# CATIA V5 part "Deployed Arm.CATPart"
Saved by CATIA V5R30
Part number: 2
Bounding box of the stored display mesh (mm): x -9.4 to 9.4, y -9.4 to 9.4, z -10 to 465
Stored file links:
  D:\OneDrive\OneDrive - Carleton University\Courses\aero2001\Design Project\3D Models\Deployed\Deployed Arm.CATPart
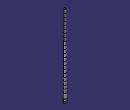
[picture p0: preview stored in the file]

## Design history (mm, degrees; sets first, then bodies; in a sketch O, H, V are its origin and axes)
Body1 (main body)
  Sketch1 on xy-plane, origin (0, 0, 0), H (1, 0, 0), V (0, 1, 0)
    circle A1 centre (0, 0) radius 9
    radius A1 = 9
  Pad1: profile Sketch1, direction (0, 0, 1), length 10, thin wall 0, second thickness 0.2
  Sketch2 on xy-plane, origin (0, 0, 0), H (1, 0, 0), V (0, 1, 0)
    circle A1 centre (0, 0) radius 8.8
    radius A1 = 8.8
  Pad2: profile Sketch2, direction (0, 0, 1), length 40, thin wall 0, second thickness 0.2
  Sketch3 on xy-plane, origin (0, 0, 0), H (1, 0, 0), V (0, 1, 0)
    circle A1 centre (0, 0) radius 8.6
    radius A1 = 8.6
  Pad3: profile Sketch3, direction (0, 0, 1), length 60, thin wall 0, second thickness 0.2
  Sketch4 on xy-plane, origin (0, 0, 0), H (1, 0, 0), V (0, 1, 0)
    circle A1 centre (0, 0) radius 8.4
    radius A1 = 8.4
  Pad4: profile Sketch4, direction (0, 0, 1), length 80, thin wall 0, second thickness 0.2
  Sketch5 on xy-plane, origin (0, 0, 0), H (1, 0, 0), V (0, 1, 0)
    circle A1 centre (0, 0) radius 8.2
    radius A1 = 8.2
  Pad5: profile Sketch5, direction (0, 0, 1), length 100, thin wall 0, second thickness 0.2
  Sketch6 on xy-plane, origin (0, 0, 0), H (1, 0, 0), V (0, 1, 0)
    circle A1 centre (0, 0) radius 8
    radius A1 = 8
  Pad6: profile Sketch6, direction (0, 0, 1), length 120, thin wall 0, second thickness 0.2
  Sketch7 on xy-plane, origin (0, 0, 0), H (1, 0, 0), V (0, 1, 0)
    circle A1 centre (0, 0) radius 7.8
    radius A1 = 7.8
  Pad7: profile Sketch7, direction (0, 0, 1), length 140, thin wall 0, second thickness 0.2
  Sketch8 on xy-plane, origin (0, 0, 0), H (1, 0, 0), V (0, 1, 0)
    circle A1 centre (0, 0) radius 7.6
    radius A1 = 7.6
  Pad8: profile Sketch8, direction (0, 0, 1), length 160, thin wall 0, second thickness 0.2
  Sketch9 on xy-plane, origin (0, 0, 0), H (1, 0, 0), V (0, 1, 0)
    circle A1 centre (0, 0) radius 7.4
    radius A1 = 7.4
  Pad9: profile Sketch9, direction (0, 0, 1), length 180, thin wall 0, second thickness 0.2
  Sketch10 on xy-plane, origin (0, 0, 0), H (1, 0, 0), V (0, 1, 0)
    circle A1 centre (0, 0) radius 7.2
    radius A1 = 7.2
  Pad10: profile Sketch10, direction (0, 0, 1), length 200, thin wall 0, second thickness 0.2
  Sketch11 on xy-plane, origin (0, 0, 0), H (1, 0, 0), V (0, 1, 0)
    circle A1 centre (0, 0) radius 7
    radius A1 = 7
  Pad11: profile Sketch11, direction (0, 0, 1), length 220, thin wall 0, second thickness 0.2
  Sketch12 on xy-plane, origin (0, 0, 0), H (1, 0, 0), V (0, 1, 0)
    circle A1 centre (0, 0) radius 6.8
    radius A1 = 6.8
  Pad12: profile Sketch12, direction (0, 0, 1), length 240, thin wall 0, second thickness 0.2
  Sketch13 on xy-plane, origin (0, 0, 0), H (1, 0, 0), V (0, 1, 0)
    circle A1 centre (0, 0) radius 6.6
    radius A1 = 6.6
  Pad13: profile Sketch13, direction (0, 0, 1), length 260, thin wall 0, second thickness 0.2
  Sketch14 on xy-plane, origin (0, 0, 0), H (1, 0, 0), V (0, 1, 0)
    circle A1 centre (0, 0) radius 6.4
    radius A1 = 6.4
  Pad14: profile Sketch14, direction (0, 0, 1), length 280, thin wall 0, second thickness 0.2
  Sketch15 on xy-plane, origin (0, 0, 0), H (1, 0, 0), V (0, 1, 0)
    circle A1 centre (0, 0) radius 6.2
    point P1 (0, 6.2)
    radius A1 = 6.2
    coincidence: A1 P1, P1 V
  Pad15: profile Sketch15, direction (0, 0, 1), length 300, thin wall 0, second thickness 0.2
  Sketch16 on xy-plane, origin (0, 0, 0), H (1, 0, 0), V (0, 1, 0)
    circle A1 centre (0, 0) radius 6
    radius A1 = 6
  Pad16: profile Sketch16, direction (0, 0, 1), length 320, thin wall 0, second thickness 0.2
  Sketch17 on xy-plane, origin (0, 0, 0), H (1, 0, 0), V (0, 1, 0)
    circle A1 centre (0, 0) radius 5.8
    radius A1 = 5.8
  Pad17: profile Sketch17, direction (0, 0, 1), length 340, thin wall 0, second thickness 0.2
  Sketch18 on xy-plane, origin (0, 0, 0), H (1, 0, 0), V (0, 1, 0)
    circle A1 centre (0, 0) radius 5.6
    radius A1 = 5.6
  Pad18: profile Sketch18, direction (0, 0, 1), length 360, thin wall 0, second thickness 0.2
  Sketch19 on xy-plane, origin (0, 0, 0), H (1, 0, 0), V (0, 1, 0)
    circle A1 centre (0, 0) radius 5.4
    radius A1 = 5.4
  Pad19: profile Sketch19, direction (0, 0, 1), length 380, thin wall 0, second thickness 0.2
  Sketch20 on xy-plane, origin (0, 0, 0), H (1, 0, 0), V (0, 1, 0)
    circle A1 centre (0, 0) radius 5.2
    radius A1 = 5.2
  Pad20: profile Sketch20, direction (0, 0, 1), length 400, thin wall 0, second thickness 0.2
  Sketch21 on xy-plane, origin (0, 0, 0), H (1, 0, 0), V (0, 1, 0)
    circle A1 centre (0, 0) radius 5
    radius A1 = 5
  Pad21: profile Sketch21, direction (0, 0, 1), length 420, thin wall 0, second thickness 0.2
  Sketch22 on xy-plane, origin (0, 0, 0), H (1, 0, 0), V (0, 1, 0)
    circle A1 centre (0, 0) radius 4.8
    radius A1 = 4.8
  Pad22: profile Sketch22, direction (0, 0, 1), length 440, thin wall 0, second thickness 0.2
  Sketch23 on xy-plane, origin (0, 0, 0), H (1, 0, 0), V (0, 1, 0)
    circle A1 centre (0, 0) radius 4.6
    radius A1 = 4.6
  Pad23: profile Sketch23, direction (0, 0, 1), length 460, thin wall 0, second thickness 0.2
  Sketch24 on xy-plane, origin (0, 0, 0), H (1, 0, 0), V (0, 1, 0)
    circle A1 centre (0, 0) radius 4.2
    radius A1 = 4.2
  Pad24: profile Sketch24, direction (0, 0, 1), length 465
  Sketch25 on yz-plane, origin (0, 0, 0), H (0, 1, 0), V (0, 0, 1)
    circle A1 centre (0, 490) radius 0.765
    radius A1 = 0.765
  Pocket1: profile Sketch25, direction (-1, 0, 0), length 6.35, mirrored extent
  Sketch26 on xy-plane, origin (0, 0, 0), H (1, 0, 0), V (0, 1, 0)
    circle A1 centre (0, 0) radius 9.4
    radius A1 = 9.4
  Pad25: profile Sketch26, direction (0, 0, -1), length 10
  Sketch27 on xy-plane, origin (0, 0, 0), H (1, 0, 0), V (0, 1, 0)
    circle A1 centre (0, 0) radius 9
    radius A1 = 9
  Pocket2: profile Sketch27, direction (0, 0, -1), length 9.8
  Sketch28 on xy-plane, origin (0, 0, 0), H (1, 0, 0), V (0, 1, 0)
    circle A1 centre (0, 0) radius 4
    radius A1 = 4
  Pocket3: profile Sketch28, direction (0, 0, 1), length 460
  Sketch29 on xy-plane, origin (0, 0, 0), H (1, 0, 0), V (0, 1, 0)
    circle A1 centre (0, 0) radius 7.55
    radius A1 = 7.55
  Pocket4: profile Sketch29, direction (0, 0, 1), length 160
